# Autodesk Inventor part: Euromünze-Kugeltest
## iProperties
Created: 2005-06
Part Number: Euromünze-Kugeltest
Material: Gold
Document SubType Name: Modeling
Designer: rsc
Manufacturer: Standard
Standards Organization: Custom
Kanten: brechen
Oberflächen: Ra 3,2
Radien: 2
Toleranzen: ISO 2768 - m
Author: rsc
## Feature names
1. Drehung1 [Revolution]
2. Trennen2
3. Trennen3
